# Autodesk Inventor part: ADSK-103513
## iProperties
Shininess: 20.0
Created: 2001-03
Part Number: ADSK-103513
Document SubType Name: Modeling
Designer: Administrator
Stock Number: ADSK-103513
Density: 1 g/cm^3
Density: 0.0
Volumn: 0.0
Area: 0.0
PropertySet Name: Model Information
Control State: 0
Master: False
Checked Out: False
Author: Administrator
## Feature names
1. Extrusion1
2. Shell1
3. Extrusion3
4. Extrusion4
5. Extrusion5
6. Hole1
7. Rectangular Pattern1
8. Extrusion6
9. Extrusion7
10. Hole2
11. Rectangular Pattern2
12. Extrusion8
13. Extrusion9
14. Extrusion10
15. Hole3
16. Hole4
17. Extrusion11
18. Extrusion12
19. Hole5
